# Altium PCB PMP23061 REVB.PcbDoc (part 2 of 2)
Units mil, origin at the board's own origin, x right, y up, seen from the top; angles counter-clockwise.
Board outline 3200 x 3250 mil, 2 copper layers (Top Layer, Bottom Layer), stack 64.8 mil thick; 102 components, 47 nets, 218 pads, 69 vias.
Unrouted connection lines stored in the file: 132.
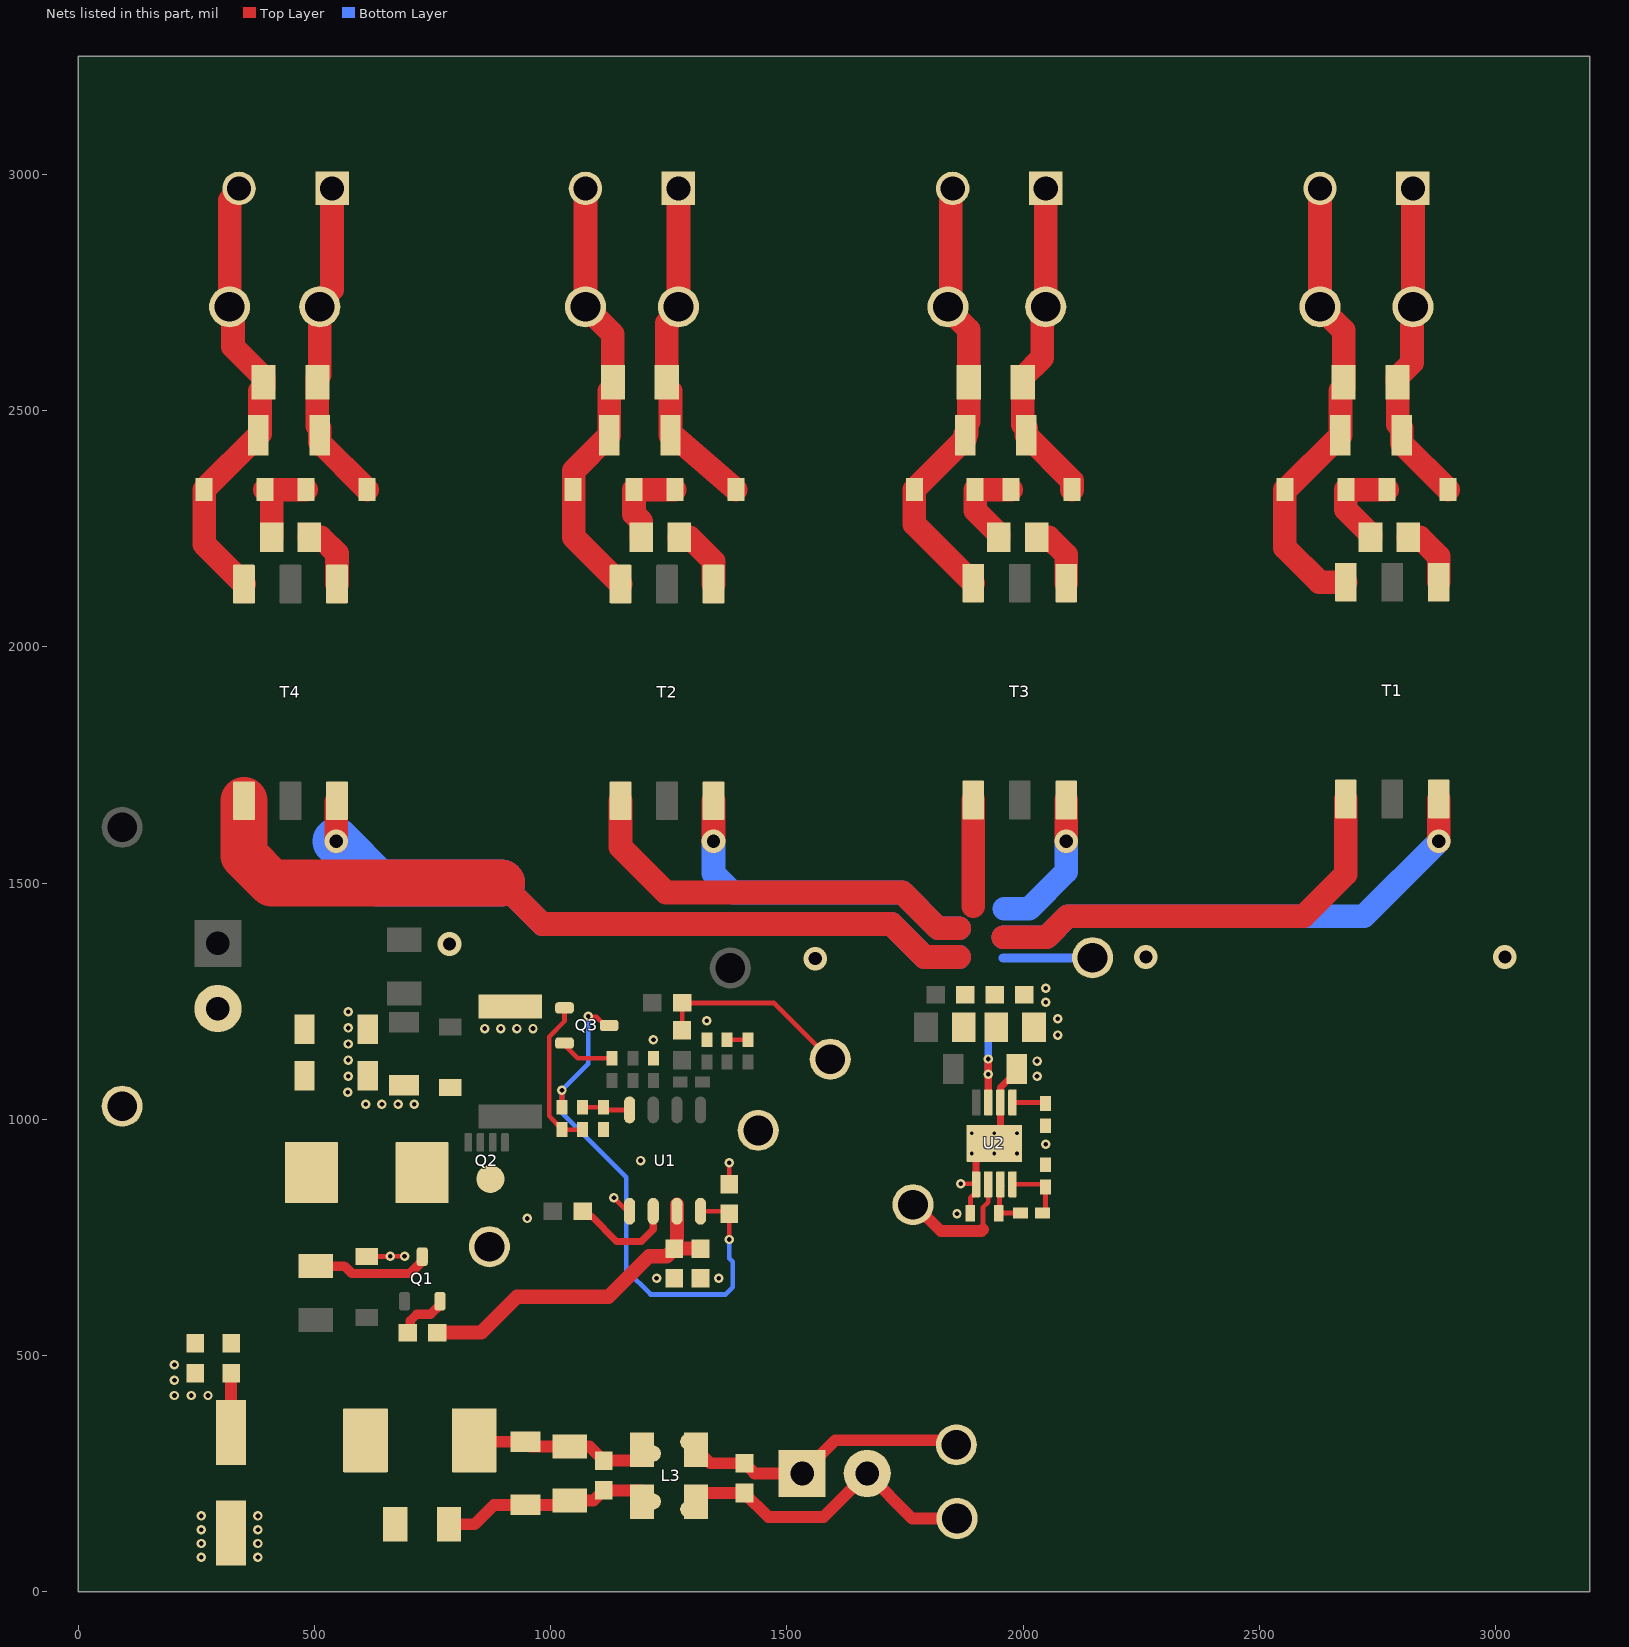
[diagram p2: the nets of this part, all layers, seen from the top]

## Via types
v1: diameter 20, hole 10, Top Layer to Bottom Layer, 55 vias
v2: diameter 50, hole 28, Top Layer to Bottom Layer, 8 vias
v3: diameter 19.68, hole 7.87, Top Layer to Bottom Layer, 6 vias

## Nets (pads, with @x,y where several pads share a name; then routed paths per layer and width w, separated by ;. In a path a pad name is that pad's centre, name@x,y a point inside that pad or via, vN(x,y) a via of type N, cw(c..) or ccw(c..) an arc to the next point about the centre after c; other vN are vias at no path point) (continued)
GND: C1.2 C2.2 C3.2 C4.2 C7.2 C8.2 C9.2 C11.1 C16.2 C17.2 C22.2 C23.2 C28.2 D2.2 J2.2 R3.1 R10.1 R14.1 R15.1 R16.1 R25.2 TP5.1 TP7.1 U1.5 U2.1 U2.6 U2.9 | length 550.5
  Top Layer w10: D2.2@610.25,709.25 659.25,709.25 v1(660,710) v1(690.32,710) ; v1(1133.63,833.79) 1162.33,805.09 U1.5@1166.9,805.09 ; C7.2@1378.11,862.65 v1(1378.11,907.61) ; v1(1868.1,863.38) 1899.41,863.38 U2.1@1900.59,862.2 1900.59,843.5 1896.73,839.65 1894.36,839.65 1888.39,833.68 C16.2@1888.39,801.18
  Top Layer w15: U2.1@1900.59,862.2 1900.59,910.43 U2.9@1938.98,948.82 1951.77,961.61 U2.6@1951.77,1035.43 1951.77,1066.86 1986.22,1101.31 C11.1@1986.22,1106.3
  other v1: 260,72.52 380,72.52 260,101.68 380,101.68 260,130.84 380,130.84 260,160 380,160 203.09,415 238.68,415 274.28,415 203.09,447.5 203.09,480 1223.9,663.08 1355.6,663.08 950,790 1860.01,800 1190,912.37 2047.81,947.21 608.46,1031.41 642.52,1031.41 676.57,1031.41 710.63,1031.41 570.22,1057.06 570.88,1091.11 2029.53,1090.73 2029.53,1123.01 570.88,1125.17 570.88,1159.22 1217.29,1168.28 2073.58,1178.2 860.17,1191.9 894.23,1191.9 928.28,1191.9 962.34,1191.9 570.88,1193.28 1330.35,1208.18 2073.58,1212.5 570.88,1227.33 2047.81,1247.43 2047.81,1277.03
  other v2: 1560,1340 2260,1343.33 3020,1343.33 785.43,1371.03
  other v3: 1890.94,927.17 1938.98,927.17 1987.01,927.17 1890.94,970.47 1938.98,970.47 1987.01,970.47
GT_DRV: R6.1 U1.6 | length 213.3
  Top Layer w15: R6.1@1075.78,797.57 1079.46,793.89 1086.98,793.89 1139.46,741.41 1191.67,741.41 1216.9,766.64 U1.6@1216.9,805.09
HB: C10.2 C17.1 R12.1 R16.2 T1.6 T2.6 T3.6 T4.6 | length 3774.6
  Top Layer w25: C10.2@1874.42,1194.88 C10.2@1876.07,1196.54 ; R12.1@1876.07,1262.13 R12.1@1877.73,1263.78
  Top Layer w50: 894.98,1500 981.77,1413.22 1721.23,1413.22 1791.11,1343.33 1864.88,1343.33 ; T2.6@1147.66,1674.02 1147.66,1576.33 1243.99,1480 1744.39,1480 1820,1404.39 1864.88,1404.39 ; 1894.39,1450.7 T3.6@1894.39,1675.98 ; 1958.23,1384.95 2049.46,1384.95 2094.52,1430 2594.3,1430 2683.09,1518.79 T1.6@2683.09,1677.95
  Top Layer w100: T4.6@350.41,1674.02 350.41,1558.58 408.99,1500 894.98,1500
NetC6_2: C6.2 R9.1 | length 44.2
  Top Layer w10: C6.2@1373.39,1168.28 1373.59,1168.09 R9.1@1417.49,1168.09
NetC12_1: C12.1 D3.1 J3.1 R18.2 TP9.1 | length 695.6
  Top Layer w50: J3.1@2825.37,2970.73 TP9.1@2825.37,2720 2823.29,2717.92 2823.29,2601.5 2792.61,2570.83 R18.2@2792.61,2560 2793.2,2559.41 2793.2,2471.48 2801.75,2462.93 C12.1@2801.75,2447.97 2801.75,2430.95 D3.1@2899.68,2333.02
NetC12_2: C12.2 D5.2 J3.2 R18.1 T1.1 TP13.1 | length 993.5
  Top Layer w50: J3.2@2628.52,2970.73 TP13.1@2628.52,2720 2678.44,2670.08 R18.1@2678.44,2560 2678.44,2549.17 2671.83,2542.56 C12.2@2671.83,2447.97 2556.87,2333.02 D5.2@2554.21,2333.02 2554.21,2210 2627.2,2137.01 T1.1@2683.09,2137.01
NetC13_1: C13.1 D4.1 J5.1 R19.2 TP10.1 | length 711.5
  Top Layer w50: C13.1@1253.48,2447.97 1253.48,2541.3 1245.61,2549.17 R19.2@1245.61,2560 1245.61,2685.34 1270.25,2709.99 TP10.1@1270.25,2720 J5.1@1270.25,2970.73 ; C13.1@1259.39,2447.97 D4.1@1391.69,2333.02
NetC13_2: C13.2 D6.2 J5.2 R19.1 T2.1 TP14.1 | length 937.3
  Top Layer w50: J5.2@1073.4,2970.73 TP14.1@1073.4,2720 1131.43,2661.97 R19.1@1131.43,2560 1131.43,2549.17 1123.56,2541.3 C13.2@1123.56,2447.97 1048.3,2372.72 1048.3,2333.02 1048.3,2232.42 T2.1@1147.66,2133.07
NetC14_1: C14.1 T1.3 | length 135.7
  Top Layer w50: C14.1@2815.53,2232.07 2839.34,2232.07 2879.94,2191.47 T1.3@2879.94,2137.01
NetC14_2: C14.2 D3.2 D5.1 | length 210.2
  Top Layer w50: C14.2@2735.53,2232.07 2735.53,2238.57 2683.15,2290.95 D5.1@2683.15,2333.02 D3.2@2770.74,2333.02
NetC15_1: C15.1 T2.3 | length 141.9
  Top Layer w50: C15.1@1271.83,2232.07 1293.76,2232.07 1344.51,2181.32 T2.3@1344.51,2133.07
NetC15_2: C15.2 D4.2 D6.1 | length 193.9
  Top Layer w50: C15.2@1191.83,2232.07 1191.83,2265.41 1176.27,2280.97 D6.1@1176.27,2333.02 D4.2@1262.76,2333.02
NetC18_1: C18.1 D7.1 J4.1 R20.2 TP15.1 | length 701.2
  Top Layer w50: J4.1@2047.81,2970.73 TP15.1@2047.81,2720 2040.73,2712.92 2040.73,2612.46 1999.1,2570.83 R20.2@1999.1,2560 1999.1,2470.81 2006.98,2462.93 C18.1@2006.98,2447.97 2103.6,2351.35 D7.1@2103.6,2333.02
NetC18_2: C18.2 D9.2 J4.2 R20.1 T3.1 TP17.1 | length 957.4
  Top Layer w50: J4.2@1850.96,2970.73 1846.97,2966.74 1846.97,2725.85 TP17.1@1841.12,2720 1841.12,2715.23 1884.93,2671.42 R20.1@1884.93,2560 1884.93,2477.5 1880.4,2472.97 1880.4,2451.32 C18.2@1877.05,2447.97 1877.05,2440.53 D9.2@1769.55,2333.02 1769.55,2259.88 T3.1@1894.39,2135.04
NetC19_1: C19.1 D8.1 J6.1 R21.2 TP16.1 | length 694
  Top Layer w50: J6.1@536.83,2970.73 536.83,2756 510.85,2730.01 TP16.1@510.85,2720 510.85,2575.75 505.92,2570.83 R21.2@505.92,2560 505.92,2467.86 510.85,2462.93 C19.1@510.85,2447.97 510.85,2433.18 D8.1@611.01,2333.02
NetC19_2: C19.2 D10.2 J6.2 R21.1 T4.1 TP18.1 | length 962.7
  Top Layer w50: J6.2@339.98,2970.73 339.98,2965.08 320,2945.1 TP18.1@320,2720 327.08,2712.92 327.08,2635.5 391.75,2570.83 R21.1@391.75,2560 391.75,2549.17 384.27,2541.7 384.27,2451.32 C19.2@380.93,2447.97 265.97,2333.02 265.97,2217.51 T4.1@350.41,2133.07
NetC20_1: C20.1 T3.3 | length 137.7
  Top Layer w50: C20.1@2028.76,2232.07 2054.06,2232.07 2091.24,2194.9 T3.3@2091.24,2135.04
NetC20_2: C20.2 D7.2 D9.1 | length 198
  Top Layer w50: C20.2@1948.76,2232.07 1948.76,2238.57 1898.48,2288.84 D9.1@1898.48,2333.02 D7.2@1974.66,2333.02
NetC21_1: C21.1 T4.3 | length 137.4
  Top Layer w50: C21.1@488.84,2232.07 513,2232.07 547.26,2197.8 T4.3@547.26,2133.07
NetC21_2: C21.2 D8.2 D10.1 | length 193.9
  Top Layer w50: C21.2@408.84,2232.07 408.84,2319.09 394.91,2333.02 D8.2@482.07,2333.02
NetC23_1: C23.1 R26.1 | length 126.1
  Top Layer w25: C23.1@323.18,336.3 R26.1@323.18,462.36
NetC24_2: C24.2 J1.2 L3.4 R23.1 TP4.1 | length 681.3
  Top Layer w25: L3.4@1291.55,173.99 1326.06,208.5 C24.2@1410,208.5 1460.5,158 1578,158 J1.2@1670,250 1765.43,154.57 TP4.1@1860.01,154.57
NetC25_2: C25.2 C26.2 C27.2 L3.3 R23.2 R25.1 | length 470.5
  Top Layer w25: R25.1@784.67,142.26 838.6,142.26 879.78,183.44 C27.2@946.27,183.44 1030.52,183.44 C26.2@1040,192.91 1090.62,192.91 C25.2@1111.8,214.09 1192.38,214.09 L3.3@1215.76,190.72
NetQ1_2: Q1.2 R4.2 | length 111.8
  Top Layer w20: R4.2@696.87,548.2 702.6,553.94 702.6,573.34 716.16,586.9 745.52,586.9 765.26,606.64 Q1.2@765.26,614.51
NetQ3_2: Q3.2 R11.1 | length 116.5
  Top Layer w10: Q3.2@1025.78,1160.4 1057.19,1128.99 R11.1@1129.29,1128.99
NetR15_2: R15.2 U2.5 | length 70.7
  Top Layer w10: U2.5@1977.36,1035.43 2045.28,1035.43 R15.2@2047.24,1033.46
NetTP11_1: TP11.1 U2.2 | length 272.6
  Top Layer w10: 1915.05,766.7 1915.05,813.55 1926.18,824.68 U2.2@1926.18,862.2
  Top Layer w25: TP11.1@1767.05,819.02 1770.18,819.02 1825.89,763.31 1911.65,763.31 1915.05,766.7
OC_DT: R13.1 R14.2 U2.4 | length 129.9
  Top Layer w10: U2.4@1977.36,862.2 2041.34,862.2 R14.2@2047.24,856.3 2047.24,807.09 R13.1@2041.34,801.18
RT_CT: C8.1 R7.2 U1.4 | length 118.6
  Top Layer w10: R7.2@1067.29,1025.21 C8.1@1111.29,1025.21 1116.84,1019.66 U1.4@1166.9,1019.66 U1.4@1166.9,1002.92
SLOPE_COMP: Q3.1 R5.1 R7.1 | length 325.7
  Top Layer w10: Q3.1@1029,1235.8 1029,1207.24 996.44,1174.68 996.44,1006.78 R5.1@1023.78,977.96 R7.1@1067.29,977.96
STABILITY: R2.2 R17.1 TP6.1 | length 421.3
  Top Layer w10: R2.2@1277.69,1188.05 1278.08,1188.44 R17.1@1278.08,1246.2 1472.41,1246.2 TP6.1@1591.65,1126.96
SW: T1.4 T2.4 T3.4 T4.4 TP12.1 U2.7 | length 3988.7
  Top Layer w10: T4.4@545.55,1672.31 T4.4@547.26,1674.02
  Top Layer w15: U2.7@1926.18,1035.43 v1(1926.18,1094.99) v1(1926.18,1127.42)
  Top Layer w50: v2(545.55,1588.24) T4.4@545.55,1672.31 ; v2(1344.51,1588.24) T2.4@1344.51,1674.02 ; v2(2091.24,1588.24) T3.4@2091.24,1675.98 ; v2(2879.94,1588.24) T1.4@2879.94,1677.95
  Bottom Layer w15: v1(1926.18,1094.99) v1(1926.18,1127.42) 1926.18,1162.37
  Bottom Layer w20: 1958.23,1341.26 TP12.1@2147.13,1341.89
  Bottom Layer w50: 894.98,1500 981.77,1413.22 1721.23,1413.22 1791.11,1343.33 1864.88,1343.33 ; v2(1344.51,1588.24) 1344.51,1520.7 1385.21,1480 1744.39,1480 1820,1404.39 1864.88,1404.39 ; 1958.23,1384.95 2049.46,1384.95 2094.52,1430 2721.7,1430 v2(2879.94,1588.24) ; 1960,1445.34 2012.41,1445.34 2091.24,1524.16 v2(2091.24,1588.24)
  Bottom Layer w100: v2(545.55,1588.24) 633.8,1500 894.98,1500
SWNODE: D1.2 L1.2 Q2.5-6-7-8 TP2.1
VCC: C3.1 C4.1 R4.1 U1.7 | length 718.2
  Top Layer w30: R4.1@759.86,548.2 852.64,548.2 928.46,624.02 1121.88,624.02 1207.87,710 1245.51,710 C4.1@1261.58,726.07 ; U1.7@1267.03,819.02 1267.03,726.07 C3.1@1316.9,726.07
VIN: C24.1 J1.1 L3.1 R22.1 TP1.1 | length 628.2
  Top Layer w25: L3.1@1291.55,317.19 1337.24,271.5 C24.1@1410,271.5 1431.5,250 J1.1@1532,250 1602.37,320.37 1848.83,320.37 TP1.1@1858.65,310.55
VIN_FILTER: C1.1 C22.1 C28.1 L1.1 L2.2 Q1.3 R1.2 R26.2 | length 251.8
  Top Layer w20: R1.2@501.98,689.07 563.12,689.07 578.83,673.36 701.83,673.36 728.36,699.9 Q1.3@728.36,707.77
VIN_INT: C25.1 C26.1 C27.1 L2.1 L3.2 R22.2 | length 401.9
  Top Layer w25: L2.1@837.8,320 840.51,317.29 C27.1@946.27,317.29 956.47,307.09 C26.1@1040,307.09 1081.8,307.09 C25.1@1111.8,277.09 1200.75,277.09 L3.2@1215.76,292.1
VREF: C7.1 Q3.3 R5.2 U1.8 | length 1184
  Top Layer w10: v1(1023.62,1061.38) 1023.7,1061.3 1023.7,1025.29 R5.2@1023.78,1025.21 ; v1(1079.28,1218.2) 1081.2,1216.28 1097.24,1216.28 1115.12,1198.4 Q3.3@1123.49,1198.4 ; U1.8@1316.9,805.09 1372.68,805.09 C7.1@1378.11,799.66 v1(1378.11,745.34) v1@1376.2,747.26
  Bottom Layer w10: v1(1079.28,1218.2) 1079.28,1117.05 v1(1023.62,1061.38) 1023.62,1013.66 1159.9,877.38 1159.9,680.31 1211.28,628.93 1369.91,628.93 1385.21,644.23 1385.21,698.14 1378.11,705.23 v1(1378.11,745.34) v1@1378.47,744.98
VREG: C16.1 R13.2 U2.3 | length 113.6
  Top Layer w10: U2.3@1955.63,858.35 U2.3@1951.77,862.2 1950.08,860.51 1950.08,802.87 C16.1@1948.39,801.18 R13.2@1994.09,801.18
pads on no net: T1.2 T1.5 T2.2 T2.5 T3.2 T3.5 T4.2 T4.5

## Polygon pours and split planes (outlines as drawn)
GND on Top Layer "TOP_LAYER_GND_P074" (solid, remove dead copper, pour order 74): 0,1380 3200,1380 3199.71,0 -0.29,0
NetC13_1 on Top Layer "TOP_LAYER_NETC13_1_P072" (solid, pour order 72): 1208.67,2289.66 1248.67,2249.66 1418.67,2249.66 1458.67,2289.66 1458.67,2559.66 1418.67,2599.66 1248.67,2599.66 1208.67,2559.66
NetC13_2 on Top Layer "TOP_LAYER_NETC13_2_P069" (solid, pour order 69): 962.05,2284.78 1002.05,2244.78 1172.05,2244.78 1212.05,2284.78 1212.05,2554.78 1172.05,2594.78 1002.05,2594.78 962.05,2554.78
VIN_FILTER on Top Layer "Top Layer-VIN_FILTER" (solid, remove dead copper, pour order 70): 650,210 680,240 680,400 650,430 560,430 400.28,589.72 400.28,690.55 440.82,650 540,650 560,670 560,1230 530,1260 450,1260 410,1220 410,1160 380,1130 190,1130 160,1100 160,540 200,500 350,500 390,460 390,250 430,210
30V on Top Layer "Top Layer-30V" (solid, remove dead copper, pour order 1): 60,1720 20,1680 20,1330 60,1290 1480,1290 1670,1100 1670,1070 1710,1030 1880,1030 1920,1070 1920,1260 1880,1300 1740.59,1300 1670.59,1370 970,1370 900,1440 390,1440 200,1630 200,1680 160,1720
NetC19_1 on Top Layer "TOP_LAYER_NETC19_1_P068" (solid, pour order 68): 444.39,2291.09 484.39,2251.09 654.39,2251.09 694.39,2291.09 694.39,2561.09 654.39,2601.09 484.39,2601.09 444.39,2561.09
NetC19_2 on Top Layer "TOP_LAYER_NETC19_2_P067" (solid, pour order 67): 199.51,2287.74 239.51,2247.74 409.51,2247.74 449.51,2287.74 449.51,2557.74 409.51,2597.74 239.51,2597.74 199.51,2557.74
NetC12_1 on Top Layer "TOP_LAYER_NETC12_1_P066" (solid, pour order 66): 2723.54,2287.74 2763.54,2247.74 2933.54,2247.74 2973.54,2287.74 2973.54,2557.74 2933.54,2597.74 2763.54,2597.74 2723.54,2557.74
NetC12_2 on Top Layer "TOP_LAYER_NETC12_2_P065" (solid, pour order 65): 2490,2295 2530,2255 2700,2255 2740,2295 2740,2565 2700,2605 2530,2605 2490,2565
NetC18_1 on Top Layer "TOP_LAYER_NETC18_1_P064" (solid, pour order 64): 1930,2293.99 1970,2253.99 2140,2253.99 2180,2293.99 2180,2563.99 2140,2603.99 1970,2603.99 1930,2563.99
NetC18_2 on Top Layer "TOP_LAYER_NETC18_2_P063" (solid, pour order 63): 1700,2290 1740,2250 1910,2250 1950,2290 1950,2560 1910,2600 1740,2600 1700,2560
CSR on Top Layer "Top Layer-CSR" (solid, pour order 51): 981.3,1033.51 849.34,1033.51 838.58,1022.75 838.58,921.33 905.53,921.33 981.3,921.33
HB on Top Layer "TOP_LAYER_HB_P027" (solid, pour order 27): 1858.65,1468.88 1839.77,1450 1839.77,1161.59 1858.65,1142.72 1954.2,1142.72 1976.84,1165.35 1978.88,1450 1960,1468.88
SWNODE on Top Layer "TOP_LAYER_SWNODE_P002" (solid, pour order 2): 592.6,761.21 608.46,745.34 801.7,745.34 842.08,710.75 915.66,710.75 915.66,764.32 915.66,898.48 829.92,984.22 829.92,1072.44 815.71,1086.65 760.11,1086.65 744.92,1071.38 744.92,1044.29 710.26,1009.63 620.15,1009.63 592.6,982.08
GND on Bottom Layer "BOTTOM_LAYER_GND_P090" (solid, remove dead copper, pour order 90): 3200,1380 0,1390 -0.7,0 3199.3,0
SW on Bottom Layer "BOTTOM_LAYER_SW_P084" (solid, pour order 84): 1960.85,1468.05 1979.72,1449.17 1979.72,1160.77 1960.85,1141.89 1865.29,1141.89 1842.65,1164.53 1840.62,1449.17 1859.49,1468.05

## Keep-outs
Keep-Out Layer:
  text ".Layer_Name" at 577,-858.49 h60

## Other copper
Top Layer:
  pour cut-out: 680,0 680,430 770,520 1990,520 2080,430 2080,0
  pour cut-out: 417.45,1020 400.68,1019.92 400.68,590 402.55,590 417.45,590
  text ".Layer_Name" at 577,-858.49 h60
Bottom Layer:
  pour cut-out: 2080,0 2080,430 1990,520 770,520 680,430 680,0
  pour cut-out: 1059.25,1450 1060,1449.25 1060,1258.69 1073.02,1258.69 1073.02,1450
  text ".Layer_Name" at 577,-858.49 h60

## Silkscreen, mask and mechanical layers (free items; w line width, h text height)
Top Overlay:
  lines w10: 1135.77,1170.58 1159.21,1194.02 1159.21,1302.31 1206.24,1349.33 1206.24,1350
  text "GND" at 413,3220 h75 r180
  text "18V" at 590.43,3220 h75 r180
  text "GND" at 1140,3220 h75 r180
  text "18V" at 1330,3220 h75 r180
  text "GND" at 1910,3220 h75 r180
  text "18V" at 2100,3220 h75 r180
  text "GND" at 2700,3220 h75 r180
  text "18V" at 2890,3220 h75 r180
  text "VBOOST" at 39.37,1539.37 h75 r270
  text "GND" at 39.37,1244.09 h75 r270
  text "'.PRJ_Number'.PCB_Rev" at 2250,30 h108.27
  text "VBATT" at 1369.91,25.49 h75
  text "GND" at 1620,25.49 h75
  text ".Layer_Name" at 577,-858.49 h60
Bottom Overlay:
  text ".Layer_Name" at 577,-858.49 h60
Top Paste:
  text ".Layer_Name" at 577,-858.49 h60
Bottom Paste:
  text ".Layer_Name" at 577,-858.49 h60
Top Solder:
  rectangle: 669.29,820.87 787.4,958.66
  rectangle: 433.07,820.87 551.18,958.66
  text ".Layer_Name" at 577,-858.49 h60
  text ".Layer_Name" at 577,-858.49 h60
Bottom Solder:
  text ".Layer_Name" at 577,-858.49 h60
Drill Guide:
  text ".Layer_Name" at 577,-858.49 h60
M1 Board Outline:
  the board outline again, w10
  text ".Layer_Name" at 577,-858.49 h60
M2 Board Dimensions:
  rectangle: 0,-275 125,-150
  rectangle: 125,-400 500,-275
  lines w7: 0,-275 1000,-275 ; 125,-400 125,-150 ; 250,-400 250,-150 ; 500,-400 500,-150 ; 750,-400 750,-150 ; 0,-400 1000,-400 1000,-150 0,-150 0,-400
  text ".Layer_Name" at 577,-858.49 h60
M3 3D STEP Top:
  text ".Layer_Name" at 577,-858.49 h60
M4 3D STEP Bottom:
  text ".Layer_Name" at 577,-858.49 h60
M5 Assembly Top:
  lines w10: -292,-930.17 6308,-930.17 ; -292,-726.83 6310,-726.83 ; -292,-523.5 -292,-1133.5 3713,-1133.5 6310,-1133.5 6310,-523.5 -291.5,-523.5 -291.5,-1133.5 1284,-1133.5 ; 2173,-1133.5 2173,-523.5 ; 3440,-726.83 3440,-523.5 ; 4280,-726.83 4280,-523.5 ; 4902,-1140 4902,-937.17
  text "COMPONENTS MARKED 'DNP' SHOULD NOT BE POPULATED." at 1153.5,-318.5 h60
  text "ASSEMBLY VARIANT:" at 1153,-434 h60
  text ".VariantName" at 2189,-434 h60
  text "PCB VIEWED FROM TOP SIDE" at -228.5,-655.67 h60
  text "BOARD #:" at 2248,-655.67 h60
  text ".PRJ_Number" at 2793.5,-655.67 h60
  text "REV:" at 3638,-655.67 h60
  text ".PCB_Rev" at 3929.5,-655.67 h60
  text "SVN REV:" at 4476,-655.67 h60
  text ".VersionControl_RevNumber" at 4982,-655.67 h60
  text "TID #:" at 2248,-859 h60
  text ".TID" at 2793.5,-859 h60
  text "PLOT NAME =" at -228.5,-1064.34 h60
  text ".plot_File_Name" at 577,-1064.34 h60
  text "GENERATED    :" at 2250,-1064.34 h60
  text ".Print_Date" at 3119.5,-1064.34 h60
  text ".Print_Time" at 3848.5,-1064.34 h60
  text "TEXAS INSTRUMENTS" at 5113,-1064.34 h60
M6 Assembly Bottom:
  lines w10: -292.5,-727.33 6309.5,-727.33 ; -290.5,-930.67 6309.5,-930.67 ; 1115.5,-1140.5 1115.5,-937.67 ; 1737.5,-727.33 1737.5,-524 ; 2577.5,-727.33 2577.5,-524 ; 3844.5,-1134 3844.5,-524 ; 4733.5,-1134 6309,-1134 6309,-524 -292.5,-524 -292.5,-1134 2304.5,-1134 6309.5,-1134 6309.5,-524
  text "COMPONENTS MARKED 'DNP' SHOULD NOT BE POPULATED." at 6102,-318 h60
  text ".VariantName" at 5058,-434 h60
  text "ASSEMBLY VARIANT:" at 6097,-434 h60
  text ".VersionControl_RevNumber" at 1035.5,-656.17 h60
  text "SVN REV:" at 1541.5,-656.17 h60
  text ".PCB_Rev" at 2088,-656.17 h60
  text "REV:" at 2379.5,-656.17 h60
  text ".PRJ_Number" at 3224,-656.17 h60
  text "BOARD #:" at 3769.5,-656.17 h60
  text "PCB VIEWED FROM BOTTOM SIDE" at 6246,-656.17 h60
  text ".TID" at 3224,-859.5 h60
  text "TID #:" at 3769.5,-859.5 h60
  text "TEXAS INSTRUMENTS" at 904.5,-1064.84 h60
  text ".Print_Time" at 2169,-1064.84 h60
  text ".Print_Date" at 2898,-1064.84 h60
  text "GENERATED    :" at 3767.5,-1064.84 h60
  text ".plot_File_Name" at 5440.5,-1064.84 h60
  text "PLOT NAME =" at 6246,-1064.84 h60
M9 Title Sheet:
  drawing of 57 lines, arcs and shapes, not listed
  text "1" at 739.84,8036.5 h70
  text "2" at 3235.5,8036.5 h70
  text "3" at 5724.84,8036.5 h70
  text "4" at 8231.51,8036.5 h70
  text "5" at 10730.5,8036.5 h70
  text "6" at 13235.5,8036.5 h70
  text "A" at -416.5,6893.5 h70
  text "A" at 14383.5,6893.5 h70
  text "B" at -416.5,4513.5 h70
  text "B" at 14383.5,4513.5 h70
  text "C" at -416.5,2138.5 h70
  text "C" at 14383.5,2138.5 h70
  text "PROJECT TITLE:" at 11343.5,277.5 h45
  text ".PRJ_Title" at 11393.5,144.17 h70
  text "DESIGNED FOR:" at 11343.5,-23.5 h45
  text ".PRJ_Customer" at 11393.5,-163.5 h70
  text "D" at -416.5,-231.5 h70
  text "D" at 14383.5,-231.5 h70
  text "FILE NAME:" at 11343.5,-323.5 h45
  text ".PCB_File_Name_No_Path" at 11393.5,-443.5 h70
  text "Texas Instruments (TI) and/or its licensors do not warrant the accuracy or completeness of this specification" at 6374,-605.34 h45
  text "ENGINEER:" at 11343.5,-613.5 h45
  text "LAYOUT BY:" at 12848.5,-613.5 h45
  text "or any information contained therein. TI and/or its licensors do not warrant that this design will meet" at 6329.01,-718 h45
  text ".PRJ_Engineer" at 11393.5,-768.49 h70
  text ".PCB_Layout" at 12899,-768.49 h70
  text "the specifications, will be suitable for your application or fit for any particular purpose, or will operate in" at 6329.01,-830.67 h45
  text ".Layer_Name" at 577,-858.49 h60
  text "ALTIUM DESIGNER VERSION:" at 12848.5,-923.5 h45
  text "an implementation. TI and/or its licensors do not warrant that the design is production worthy. You should" at 6329.01,-943.33 h45
  text "completely validate and test your design implementation to confirm the system functionality for your application." at 6374,-1056 h45
  text ".print_Scale" at 11393.5,-1056.83 h70
  text ".Application_BuildNumber" at 12899,-1056.83 h70
  text "1" at 739.84,-1263.5 h70
  text "2" at 3235.5,-1263.5 h70
  text "3" at 5724.84,-1263.5 h70
  text "4" at 8231.51,-1263.5 h70
  text "5" at 10730.5,-1263.5 h70
  text "6" at 13235.5,-1263.5 h70
M10 Fab Notes:
  drawing of 189 lines, arcs and shapes, not listed
  text "DESIGN INFORMATION" at 12382.02,6356.17 h60
  text "MIN. TRACK WIDTH:" at 11737.46,6224.05 h60
  text "10" at 12833.7,6224.05 h60
  text "MIL" at 12988.46,6224.05 h60
  text "7.874" at 12667.32,6102.36 h60
  text "MIN. CLEARANCE:" at 11737.46,6099.92 h60
  text "MIL" at 12988.46,6099.92 h60
  text "MIN. VIA PAD SIZE:" at 11737.46,5975.8 h60
  text "24" at 12803.71,5975.8 h60
  text "MIL" at 12988.46,5975.8 h60
  text "0.05mm (2MIL)" at 12432.46,5845.9 h60
  text "MINIMUM ANNULAR RING" at 11408.23,5837.67 h60
  text "EXTERNAL" at 13140.46,5837.67 h60
  text "PER" at 11608.23,5727.55 h60
  text "IPC-D-275 CLASS 2 LEVEL C" at 11828.23,5727.54 h60
  text "MIL, HOLES" at 13316.46,5627.07 h60
  text "+/-" at 12924,5618.48 h60
  text "+/-" at 13778,5618.48 h60
  text "REGISTRATION TOLERANCES:" at 11408.23,5617.42 h60
  text "METAL" at 12608,5617.42 h60
  text "5" at 13184.2,5617.42 h60
  text "3" at 14017.2,5617.42 h60
  text "MIL" at 14133.46,5617.42 h60
  text "HOLE SIZE TOLERANCE (UNLESS OTHERWISE SPECIFIED):" at 11408.23,5519.1 h60
  text "+/-" at 13778,5516.23 h60
  text "3" at 14017.2,5515.17 h60
  text "MIL" at 14133.46,5515.17 h60
  text "MATERIAL:" at 11333.46,5377.52 h60
  text "FR-4 High Tg" at 12319.9,5249 h60
  text "X" at 12175.46,5241.01 h60
  text "FR-408" at 11754.46,5236.49 h60
  text "OTHER" at 13242.46,5236.49 h60
  text "62 MIL (1.6mm) +/-10%" at 12074.56,5093.46 h60
  text "X" at 11954.46,5091.01 h60
  text "THICKNESS:" at 11408.23,5085.24 h60
  text "OTHER" at 13359.46,5085.24 h60
  text "TOLERANCE:" at 11408.23,4946.92 h60
  text "X" at 12256.46,4946.92 h60
  text "ANSI IPC-6012 TYPE 3 CLASS 2" at 12434.48,4946.92 h60
  text "OTHER +/-" at 12434.46,4802.73 h60
  text "BOW & TWIST:" at 11408.23,4657.54 h60
  text "X" at 12256.46,4657.54 h60
  text "ANSI IPC-6012 TYPE 3 CLASS 2" at 12434.48,4657.54 h60
  text "OTHER +/-" at 12434.46,4510.85 h60
  text "DRILLING:" at 11333.46,4380.23 h60
  text "NC_DRILL FILES" at 13094.46,4275.04 h60
  text "REFERENCE:" at 11408.23,4271.1 h60
  text "X" at 12065.46,4271.01 h60
  text "AS SHOWN" at 12243.46,4271.1 h60
  text "X" at 12966.46,4271.1 h60
  text "OTHER" at 13392.46,4128.85 h60
  text "PTH COPPER THICKNESS:" at 11407.91,4125.32 h60
  text "X" at 12547.14,4125.32 h60
  text "20-30 um" at 12675.14,4125.32 h60
  text "BOARD FINISH:" at 11333.46,3977.73 h60
  text "SILKSCREEN:" at 11488.68,3867.6 h60
  text "X" at 12446.46,3867.6 h60
  text "TOP" at 12563.46,3867.6 h60
  text "X" at 12956.46,3867.6 h60
  text "BOTTOM" at 13074.46,3867.6 h60
  text "SILKSCREEN COLOR:" at 11488.68,3712.41 h60
  text "X" at 12445.46,3712.41 h60
  text "WHITE" at 12563.46,3712.41 h60
  text "OTHER" at 13074.46,3712.41 h60
  text "X" at 12576.46,3568.96 h60
  text "GREEN" at 12694.46,3568.96 h60
  text "OTHER" at 13312.46,3568.96 h60
  text "SOLDER RESIST COLOR:" at 11488.68,3562.1 h60
  text "X" at 12576.46,3414.71 h60
  text "MATTE" at 12694.46,3414.71 h60
  text "SEMI-GLOSS" at 13312,3414.07 h60
  text "IMMERSION GOLD (ENIG)" at 12394.46,3241.94 h60
  text "ENEPIG" at 13732,3234.72 h60
  text "SURFACE FINISH:" at 11333.46,3233.72 h60
  text "X" at 12216.46,3233.72 h60
  text "IMM. TIN/SILVER OR EQUIV" at 11663,3096.4 h60
  text "OTHER" at 13094.46,3092.47 h60
  text "ARRAY/PANEL:" at 11333.46,2937.09 h60
  text "CUT AND TRIM PER M1 BOARD OUTLINE" at 12394.46,2928.87 h60
  text "N.C. ROUTE" at 12394.46,2792.9 h60
  text "X" at 13082.46,2792.9 h60
  text "V. SCORE" at 13260.46,2792.9 h60
  text "CERTIFICATION:" at 11333.46,2663.77 h60
  text "MATERIALS AND WORKMANSHIP FOR ALL PCBS" at 12058.46,2663.77 h60
  text "TO MEET OR EXCEED THE REQUIREMENTS OF:" at 12058.46,2569.71 h60
  text "X" at 11695.97,2441.08 h60
  text "ANSI IPC-A-600F CLASS ->" at 11823.96,2441.08 h60
  text "X" at 13471.97,2441.08 h60
  text "2" at 13581.96,2441.08 h60
  text "1" at 13266.96,2439.58 h60
  text "3" at 13935.96,2439.58 h60
  text "X" at 12507.97,2293.39 h60
  text "RoHS" at 12635.96,2293.39 h60
  text "OTHER" at 13280.36,2293.39 h60
  text "PER ORDER" at 13677.42,2293.39 h60
  text "ALL BOARDS MUST MEET OR EXCEED UL94-V0 REQUIREMENTS." at 11361,2139.57 h60
  text "PCB MUST BEAR THE UL94V-0 UL REGISTERED MATERIAL ID NUMBER" at 11361,2023.5 h60
  text "ADDITIONAL REQUIREMENTS:" at 11333.46,1854.08 h60
  text "MICROSECTION:" at 11408.23,1746.95 h60
  text "YES" at 12313.96,1746.95 h60
  text "REQUIRED" at 13175.46,1602.62 h60
  text "BARE BOARD ELEC. TEST:" at 11408.23,1599.76 h60
  text "NONE" at 12713.96,1599.76 h60
  text "X" at 13057.46,1599.76 h60
  text "PER ORDER" at 13767.46,1599.76 h60
  text "XX MIL VIAS REQUIRE NON-CONDUCTIVE FILL AND PLANARIZE" at 11576.38,1394.82 h59
  text "XX MIL VIAS REQUIRE CONDUCTIVE FILL AND PLANARIZE" at 11584.38,1290.84 h60
  text "OUTER XX MIL TRACES REQUIRE 50 OHM SINGLE-ENDED IMPEDANCE" at 11583.39,1127.46 h58
  text "LAYER 2 & 3 (INNER LAYERS) XX MIL WIDE, XX MIL SPACE / TRACES REQUIRE 100 OHM DIFFERENTIAL IMPEDANCE" at 11575.39,891.74 h60
  text ".Layer_Name" at 577,-858.49 h60
M11 Gerber Information:
  lines w10: -292,-930.17 6308,-930.17 ; -292,-726.83 6310,-726.83 ; -292,-523.5 -292,-1133.5 3713,-1133.5 6310,-1133.5 6310,-523.5 -291.5,-523.5 -291.5,-1133.5 1284,-1133.5 ; 2173,-1133.5 2173,-523.5 ; 3440,-726.83 3440,-523.5 ; 4280,-726.83 4280,-523.5 ; 4902,-1140 4902,-937.17
  text "ALL ARTWORK VIEWED FROM TOP SIDE" at -228.5,-655.67 h60
  text "BOARD #:" at 2248,-655.67 h60
  text ".PRJ_Number" at 2793.5,-655.67 h60
  text "REV:" at 3638,-655.67 h60
  text ".PCB_Rev" at 3929.5,-655.67 h60
  text "SVN REV:" at 4476,-655.67 h60
  text ".VersionControl_RevNumber" at 4982,-655.67 h60
  text "LAYER NAME =" at -228.5,-858.49 h60
  text "TID #:" at 2248,-859 h60
  text ".TID" at 2793.5,-859 h60
  text "PLOT NAME =" at -228.5,-1064.34 h60
  text ".plot_File_Name" at 577,-1064.34 h60
  text "GENERATED    :" at 2250,-1064.34 h60
  text ".Print_Date" at 3119.5,-1064.34 h60
  text ".Print_Time" at 3848.5,-1064.34 h60
  text "TEXAS INSTRUMENTS" at 5113,-1064.34 h60
M12 Stackup:
  drawing of 191 lines, arcs and shapes, not listed
  text "Layer" at 9760.58,7810 h60
  text "Name" at 10170.49,7810 h60
  text "Material" at 11100.23,7810 h60
  text "Thickness" at 11960,7810 h60
  text "Constant" at 12609.84,7810 h60
  text "Board Layer Stack" at 13179.7,7810 h60
  text "Top Overlay" at 10170.49,7690 h60
  text "Top Solder" at 10170.49,7570 h60
  text "Solder Resist" at 11100.23,7570 h60
  text "0.40mil" at 11960,7570 h60
  text "3.5" at 12609.84,7570 h60
  text "1" at 9760.58,7450 h60
  text "Top Layer" at 10170.49,7450 h60
  text "2.80mil" at 11960,7450 h60
  text "Dielectric1" at 10170.49,7330 h60
  text "FR-4 High Tg" at 11100.23,7330 h60
  text "59.20mil" at 11960,7330 h60
  text "4.8" at 12609.84,7330 h60
  text "2" at 9760.58,7210 h60
  text "Bottom Layer" at 10170.49,7210 h60
  text "2.80mil" at 11960,7210 h60
  text "Bottom Solder" at 10170.49,7090 h60
  text "Solder Resist" at 11100.23,7090 h60
  text "0.40mil" at 11960,7090 h60
  text "3.5" at 12609.84,7090 h60
  text "Bottom Overlay" at 10170.49,6970 h60
  text ".Layer_Name" at 577,-858.49 h60
M13 Component Bodies Top:
  text ".Layer_Name" at 577,-858.49 h60
M14 Component Bodies Bottom:
  text ".Layer_Name" at 577,-858.49 h60
M15 Courtyards Top:
  text ".Layer_Name" at 577,-858.49 h60
M16 Courtyards Bottom:
  text ".Layer_Name" at 577,-858.49 h60
Drill Drawing:
  circle w10: c4153.72,2709.96 r27.63
  lines w10: 4126.09,2185.06 4181.34,2185.06 4181.34,2240.31 4126.09,2240.31 4126.09,2185.06 ; 4126.09,2364.63 4181.34,2364.63 4153.72,2309.38 4126.09,2364.63 ; 4126.09,2447.51 4139.9,2447.51 4139.9,2433.7 4167.53,2433.7 4167.53,2447.51 4181.34,2447.51 4181.34,2475.14 4167.53,2475.14 4167.53,2488.95 4139.9,2488.95 4139.9,2475.14 4126.09,2475.14 4126.09,2447.51 ; 4126.09,2558.02 4153.72,2571.83 4181.34,2558.02 4167.53,2585.64 4181.34,2613.27 4153.72,2599.46 4126.09,2613.27 4139.9,2585.64 4126.09,2558.02 ; 4126.09,2820.47 4139.9,2820.47 4153.72,2806.66 4167.53,2820.47 4181.34,2820.47 4167.53,2834.28 4181.34,2848.1 4167.53,2848.1 4153.72,2861.91 4139.9,2848.1 4126.09,2848.1 4139.9,2834.28 4126.09,2820.47
  lines w12: 4076,2147.76 7307.49,2147.76 ; 4076,2893.68 7307.49,2893.68 ; 4413.86,2023.44 4413.86,3018 ; 4745.86,2023.44 4745.86,3018 ; 5382.43,2023.44 5382.43,3018 ; 5641.57,2023.44 5641.57,3018 ; 6016.72,2023.44 6016.72,3018 ; 6741.05,2023.44 6741.05,3018 ; 4076,2023.44 7307.49,2023.44 7307.49,3018 4076,3018 4076,2023.44
  text "Symbol" at 4150.59,2930.98 h72
  text "Quantity" at 4451.16,2930.98 h72
  text "Finished Hole Size" at 4783.16,2930.98 h72
  text "Plated" at 5419.72,2930.98 h72
  text "Hole Type" at 5678.86,2930.98 h72
  text "Drill Layer Pair" at 6054.02,2930.98 h72
  text "Hole Tolerance" at 6778.35,2930.98 h72
  text "6" at 4451.16,2806.66 h60
  text "7.87mil (0.200mm)" at 4783.16,2806.66 h60
  text "PTH" at 5419.72,2806.66 h60
  text "Round" at 5678.86,2806.66 h60
  text "Top Layer - Bottom Layer" at 6054.02,2806.66 h60
  text "55" at 4451.16,2682.34 h60
  text "10.00mil (0.254mm)" at 4783.16,2682.34 h60
  text "PTH" at 5419.72,2682.34 h60
  text "Round" at 5678.86,2682.34 h60
  text "Top Layer - Bottom Layer" at 6054.02,2682.34 h60
  text "8" at 4451.16,2558.02 h60
  text "28.00mil (0.711mm)" at 4783.16,2558.02 h60
  text "PTH" at 5419.72,2558.02 h60
  text "Round" at 5678.86,2558.02 h60
  text "Top Layer - Bottom Layer" at 6054.02,2558.02 h60
  text "4" at 4451.16,2433.7 h60
  text "50.00mil (1.270mm)" at 4783.16,2433.7 h60
  text "PTH" at 5419.72,2433.7 h60
  text "Round" at 5678.86,2433.7 h60
  text "Top Layer - Bottom Layer" at 6054.02,2433.7 h60
  text "8" at 4451.16,2309.38 h60
  text "51.18mil (1.300mm)" at 4783.16,2309.38 h60
  text "PTH" at 5419.72,2309.38 h60
  text "Round" at 5678.86,2309.38 h60
  text "Top Layer - Bottom Layer" at 6054.02,2309.38 h60
  text "18" at 4451.16,2185.06 h60
  text "63.00mil (1.600mm)" at 4783.16,2185.06 h60
  text "PTH" at 5419.72,2185.06 h60
  text "Round" at 5678.86,2185.06 h60
  text "Top Layer - Bottom Layer" at 6054.02,2185.06 h60
  text "99 Total" at 4451.16,2060.74 h60
  text ".Layer_Name" at 577,-858.49 h60
M17 Embedded Cavity:
  text ".Layer_Name" at 577,-858.49 h60
M18 Embedded Assembly:
  text ".Layer_Name" at 577,-858.49 h60
M19 Embedded Keepout:
  text ".Layer_Name" at 577,-858.49 h60

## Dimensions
0,3250 to 0,0 on M2 Board Dimensions
-0.24,2.26 to 3199.76,2.26 on M2 Board Dimensions
0,-400 to 1000,-400 on M2 Board Dimensions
